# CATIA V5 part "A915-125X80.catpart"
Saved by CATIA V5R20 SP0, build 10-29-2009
Part number: A915-125X80
Source: Unknown
Property "A": "75.000"
Property "ARTICLENO": "A915-125X80"
Property "BOMINFO": "A915-125X80"
Property "CODE": "A915-125X80"
Property "CREATOR": "CADENAS GmbH"
Property "D": "13.500"
Property "D1": "20.000"
Property "FORM": "A"
Property "L": "80.000"
Property "L1": "40.000"
Property "L2": "0.000"
Property "LINA": "A915-125X80"
Property "NB": "A915-125X80"
Property "NBSYN": "$CODE."
Property "NN": "A915"
Property "NT": "VDI 3357 Wear Plates, steel"
Property "SCREW": "M12x25"
Property "SUPPLIER": "CF"
Property "T": "13.000"
Property "W": "125.000"
Bounding box of the stored display mesh (mm): x 0 to 20, y 0 to 80, z -62.5 to 62.5
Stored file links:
  C:\Users\borellobunino\Desktop\3D X SITO CF\A915\GSB_OILLESS_G22501125080\CATIAV5\A915-125X80.catpart
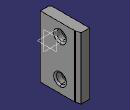
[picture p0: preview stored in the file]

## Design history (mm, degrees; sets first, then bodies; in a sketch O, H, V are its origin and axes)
Body1 "Geometry.1" (main body)
  Solid1 "A915-125X80.catpart": solid without history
